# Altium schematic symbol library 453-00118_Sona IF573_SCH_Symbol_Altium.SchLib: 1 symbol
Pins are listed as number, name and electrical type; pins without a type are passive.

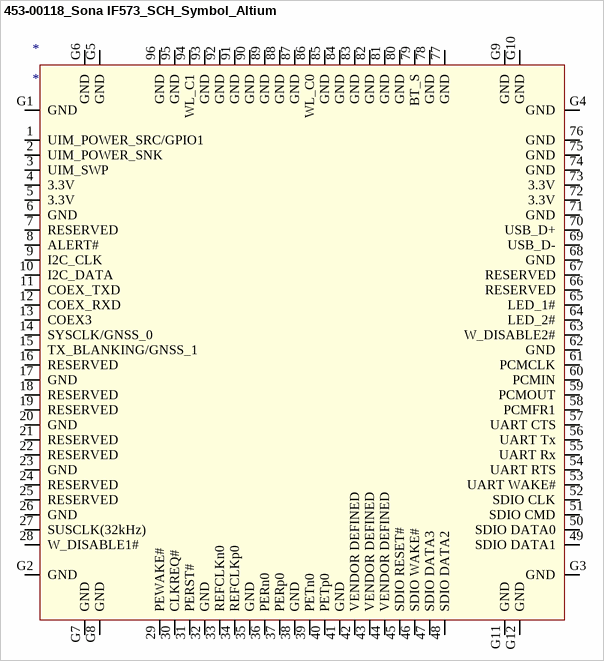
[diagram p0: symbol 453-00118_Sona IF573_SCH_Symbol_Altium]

## 453-00118_Sona IF573_SCH_Symbol_Altium
designator *
pins: 1 UIM_POWER_SRC/GPIO1, 2 UIM_POWER_SNK, 3 UIM_SWP, 4 3.3V, 5 3.3V, 6 GND, 7 RESERVED, 8 ALERT#, 9 I2C_CLK, 10 I2C_DATA, 11 COEX_TXD, 12 COEX_RXD, 13 COEX3, 14 SYSCLK/GNSS_0, 15 TX_BLANKING/GNSS_1, 16 RESERVED, 17 GND, 18 RESERVED, 19 RESERVED, 20 GND, 21 RESERVED, 22 RESERVED, 23 GND, 24 RESERVED, 25 RESERVED, 26 GND, 27 SUSCLK(32kHz), 28 W_DISABLE1#, 29 PEWAKE#, 30 CLKREQ#, 31 PERST#, 32 GND, 33 REFCLKn0, 34 REFCLKp0, 35 GND, 36 PERn0, 37 PERp0, 38 GND, 39 PETn0, 40 PETp0, 41 GND, 42 VENDOR DEFINED, 43 VENDOR DEFINED, 44 VENDOR DEFINED, 45 SDIO RESET#, 46 SDIO WAKE#, 47 SDIO DATA3, 48 SDIO DATA2, 49 SDIO DATA1, 50 SDIO DATA0, 51 SDIO CMD, 52 SDIO CLK, 53 UART WAKE#, 54 UART RTS, 55 UART Rx, 56 UART Tx, 57 UART CTS, 58 PCMFR1, 59 PCMOUT, 60 PCMIN, 61 PCMCLK, 62 GND, 63 W_DISABLE2#, 64 LED_2#, 65 LED_1#, 66 RESERVED, 67 RESERVED, 68 GND, 69 USB_D-, 70 USB_D+, 71 GND, 72 3.3V, 73 3.3V, 74 GND, 75 GND, 76 GND, 77 GND, 78 GND, 79 BT_S, 80 GND, 81 GND, 82 GND, 83 GND, 84 GND, 85 GND, 86 WL_C0, 87 GND, 88 GND, 89 GND, 90 GND, 91 GND, 92 GND, 93 GND, 94 WL_C1, 95 GND, 96 GND, G1 GND, G2 GND, G3 GND, G4 GND, G5 GND, G6 GND, G7 GND, G8 GND, G9 GND, G10 GND, G11 GND, G12 GND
